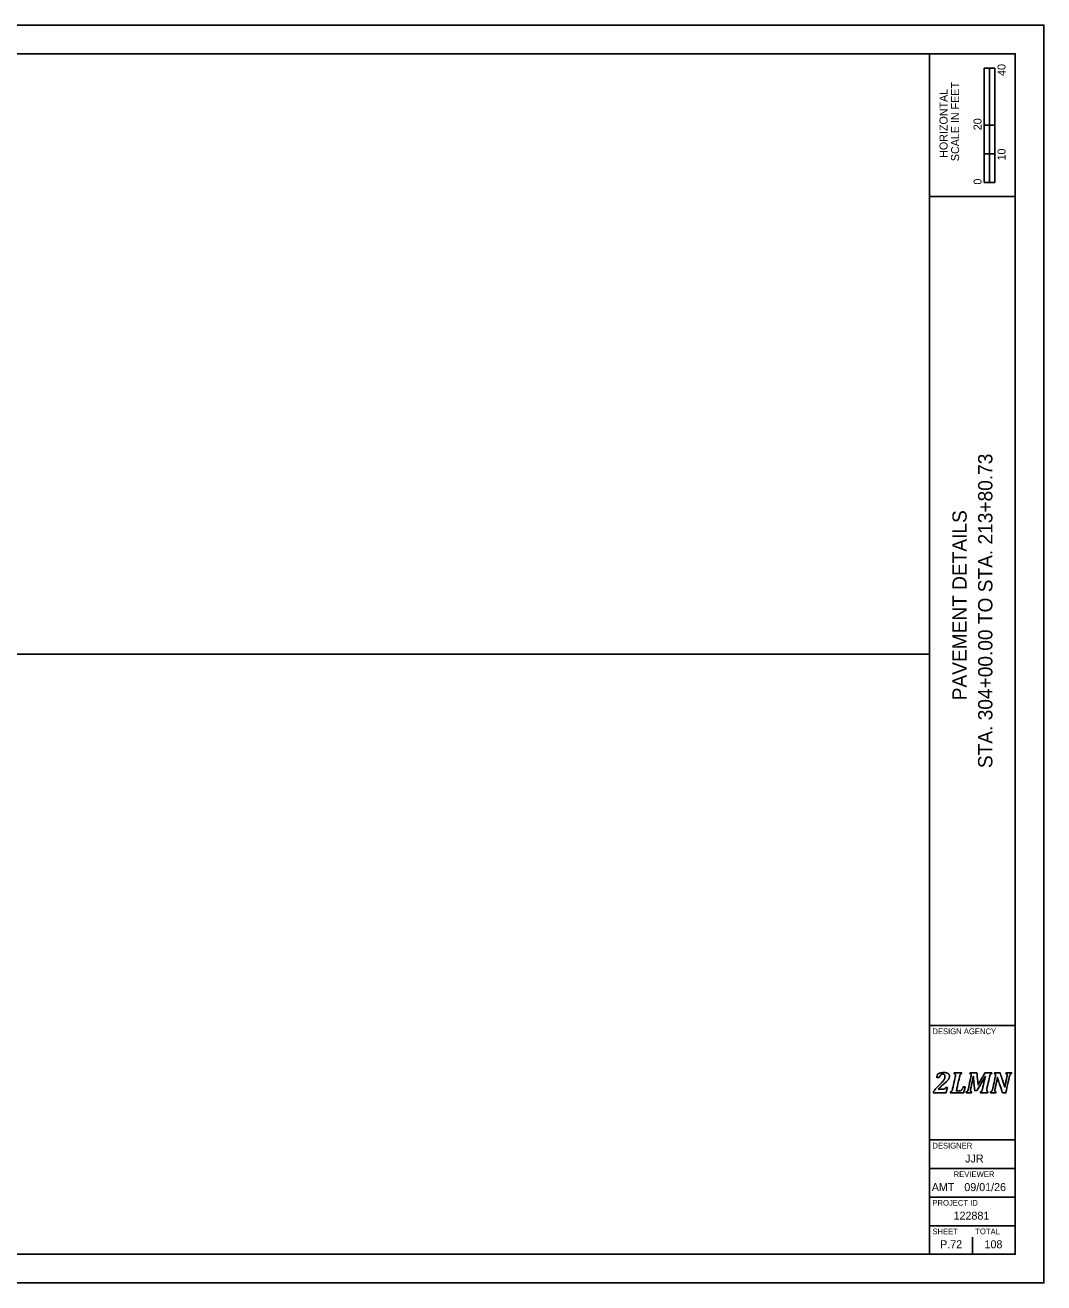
# Model space of a CAD drawing. Extents: x -1.6 to 34, y 0 to 22.
# Drawn here: x 16.18 to 34, y 0 to 22 of the extents above; entities that cross this region are included whole.
import ezdxf

# ---------------------------------------------------------------- set-up
doc = ezdxf.new("R2010")
doc.units = 0
for name, color, linetype in [('SH_Border', 7, 'Continuous'), ('SH_Cut_Line', 7, 'Continuous'), ('SH_Data', 7, 'Continuous')]:
    doc.layers.add(name, color=color, linetype=linetype)

msp = doc.modelspace()

# ---------------------------------------------------------------- linework, layer by layer
at = {"layer": 'SH_Border'}
for p, q in [((32, 0.5), (32, 21.5)), ((32, 19), (33.5, 19)), ((1.5, 11), (32, 11)), ((32, 4.5), (33.5, 4.5)), ((32, 2.5), (33.5, 2.5)), ((32, 2), (33.5, 2)), ((32, 1.5), (33.5, 1.5)), ((32, 1), (33.5, 1))]:
    msp.add_line(p, q, dxfattribs=at)
msp.add_lwpolyline([(1.5, 21.5), (33.5, 21.5), (33.5, 0.5), (1.5, 0.5)], close=True, dxfattribs=at)
at = {"layer": 'SH_Cut_Line'}
msp.add_lwpolyline([(0, 0), (34, 0), (34, 22), (0, 22)], close=True, dxfattribs=at)
at = {"layer": 'SH_Data'}
for p, q in [((32.957, 19.25), (32.957, 21.25)), ((33.144, 21.25), (32.957, 21.25)), ((32.957, 20.25), (32.957, 21.25)), ((32.957, 21.25), (33.05, 21.25)), ((33.05, 21.25), (33.051, 21.25)), ((33.051, 21.25), (33.051, 20.25)), ((33.144, 21.25), (33.144, 19.25)), ((33.051, 20.25), (32.957, 20.25)), ((33.143, 20.25), (33.05, 20.25)), ((33.05, 20.25), (33.05, 19.75)), ((33.143, 19.75), (33.143, 20.25)), ((33.05, 19.75), (32.957, 19.75)), ((32.957, 19.75), (32.957, 19.25)), ((33.05, 19.25), (33.05, 19.75)), ((33.05, 19.75), (33.143, 19.75)), ((33.144, 19.25), (32.957, 19.25)), ((32.957, 19.25), (33.05, 19.25)), ((32.75, 3.5), (32.75, 3.5)), ((32.375, 0.675), (32.375, 0.675)), ((32.75, 0.5), (32.75, 0.8))]:
    msp.add_line(p, q, dxfattribs=at)
for points in [[(32.237, 3.388), (32.246, 3.388), (32.253, 3.389), (32.258, 3.39), (32.263, 3.392), (32.267, 3.394), (32.27, 3.397), (32.273, 3.401), (32.277, 3.408), (32.281, 3.417), (32.281, 3.417), (32.312, 3.417), (32.312, 3.417), (32.312, 3.417), (32.29, 3.326), (32.29, 3.326), (32.29, 3.326), (32.066, 3.326), (32.066, 3.326), (32.066, 3.326), (32.069, 3.343), (32.069, 3.343), (32.078, 3.358), (32.091, 3.375), (32.106, 3.394), (32.122, 3.412), (32.144, 3.435), (32.172, 3.462), (32.197, 3.486), (32.217, 3.506), (32.23, 3.521), (32.243, 3.537), (32.253, 3.551), (32.259, 3.566), (32.266, 3.58), (32.269, 3.595), (32.269, 3.61), (32.269, 3.622), (32.266, 3.632), (32.26, 3.64), (32.253, 3.647), (32.245, 3.65), (32.234, 3.65), (32.22, 3.65), (32.208, 3.646), (32.198, 3.636), (32.188, 3.627), (32.18, 3.613), (32.172, 3.593), (32.172, 3.593), (32.126, 3.593), (32.126, 3.593), (32.126, 3.593), (32.14, 3.654), (32.14, 3.654), (32.166, 3.663), (32.188, 3.669), (32.205, 3.673), (32.223, 3.676), (32.24, 3.678), (32.258, 3.678), (32.278, 3.678), (32.295, 3.675), (32.309, 3.669), (32.322, 3.664), (32.332, 3.656), (32.339, 3.646), (32.345, 3.637), (32.348, 3.626), (32.348, 3.613), (32.348, 3.602), (32.346, 3.591), (32.342, 3.581), (32.339, 3.571), (32.333, 3.56), (32.324, 3.549), (32.315, 3.539), (32.304, 3.526), (32.289, 3.513), (32.275, 3.499), (32.254, 3.482), (32.228, 3.46), (32.216, 3.45), (32.202, 3.438), (32.188, 3.425), (32.174, 3.412), (32.162, 3.4), (32.154, 3.391), (32.154, 3.391), (32.153, 3.388), (32.153, 3.388), (32.153, 3.388), (32.237, 3.388), (32.237, 3.388)], [(32.237, 3.388), (32.237, 3.388), (32.153, 3.388), (32.153, 3.388), (32.153, 3.388), (32.154, 3.391), (32.154, 3.391), (32.162, 3.4), (32.174, 3.412), (32.188, 3.425), (32.202, 3.438), (32.216, 3.45), (32.228, 3.46), (32.254, 3.482), (32.275, 3.499), (32.289, 3.513), (32.304, 3.526), (32.315, 3.539), (32.324, 3.549), (32.333, 3.56), (32.339, 3.571), (32.342, 3.581), (32.346, 3.591), (32.348, 3.602), (32.348, 3.613), (32.348, 3.626), (32.345, 3.637), (32.339, 3.646), (32.332, 3.656), (32.322, 3.664), (32.309, 3.669), (32.295, 3.675), (32.278, 3.678), (32.258, 3.678), (32.24, 3.678), (32.223, 3.676), (32.205, 3.673), (32.188, 3.669), (32.166, 3.663), (32.14, 3.654), (32.14, 3.654), (32.126, 3.593), (32.126, 3.593), (32.126, 3.593), (32.172, 3.593), (32.172, 3.593), (32.18, 3.613), (32.188, 3.627), (32.198, 3.636), (32.208, 3.646), (32.22, 3.65), (32.234, 3.65), (32.245, 3.65), (32.253, 3.647), (32.26, 3.64), (32.266, 3.632), (32.269, 3.622), (32.269, 3.61), (32.269, 3.595), (32.266, 3.58), (32.259, 3.566), (32.253, 3.551), (32.243, 3.537), (32.23, 3.521), (32.217, 3.506), (32.197, 3.486), (32.172, 3.462), (32.144, 3.435), (32.122, 3.412), (32.106, 3.394), (32.091, 3.375), (32.078, 3.358), (32.069, 3.343), (32.069, 3.343), (32.066, 3.326), (32.066, 3.326), (32.066, 3.326), (32.29, 3.326), (32.29, 3.326), (32.29, 3.326), (32.312, 3.417), (32.312, 3.417), (32.312, 3.417), (32.281, 3.417), (32.281, 3.417), (32.277, 3.408), (32.273, 3.401), (32.27, 3.397), (32.267, 3.394), (32.263, 3.392), (32.258, 3.39), (32.253, 3.389), (32.246, 3.388), (32.237, 3.388)], [(32.518, 3.356), (32.527, 3.356), (32.533, 3.357), (32.538, 3.358), (32.542, 3.36), (32.546, 3.362), (32.55, 3.365), (32.554, 3.368), (32.558, 3.372), (32.562, 3.377), (32.567, 3.382), (32.571, 3.388), (32.576, 3.397), (32.58, 3.405), (32.585, 3.415), (32.589, 3.427), (32.589, 3.427), (32.624, 3.427), (32.624, 3.427), (32.624, 3.427), (32.598, 3.326), (32.598, 3.326), (32.598, 3.326), (32.365, 3.326), (32.365, 3.326), (32.365, 3.326), (32.369, 3.343), (32.369, 3.343), (32.376, 3.345), (32.381, 3.348), (32.385, 3.351), (32.389, 3.355), (32.392, 3.36), (32.395, 3.366), (32.398, 3.373), (32.4, 3.382), (32.403, 3.395), (32.403, 3.395), (32.449, 3.605), (32.449, 3.605), (32.452, 3.615), (32.453, 3.625), (32.453, 3.635), (32.453, 3.642), (32.451, 3.647), (32.448, 3.651), (32.444, 3.654), (32.439, 3.656), (32.432, 3.657), (32.432, 3.657), (32.435, 3.674), (32.435, 3.674), (32.435, 3.674), (32.563, 3.674), (32.563, 3.674), (32.563, 3.674), (32.559, 3.657), (32.559, 3.657), (32.552, 3.655), (32.547, 3.652), (32.543, 3.649), (32.539, 3.645), (32.536, 3.64), (32.533, 3.634), (32.531, 3.627), (32.528, 3.618), (32.525, 3.605), (32.525, 3.605), (32.47, 3.356), (32.47, 3.356), (32.47, 3.356), (32.518, 3.356), (32.518, 3.356)], [(32.518, 3.356), (32.518, 3.356), (32.47, 3.356), (32.47, 3.356), (32.47, 3.356), (32.525, 3.605), (32.525, 3.605), (32.528, 3.618), (32.531, 3.627), (32.533, 3.634), (32.536, 3.64), (32.539, 3.645), (32.543, 3.649), (32.547, 3.652), (32.552, 3.655), (32.559, 3.657), (32.559, 3.657), (32.563, 3.674), (32.563, 3.674), (32.563, 3.674), (32.435, 3.674), (32.435, 3.674), (32.435, 3.674), (32.432, 3.657), (32.432, 3.657), (32.439, 3.656), (32.444, 3.654), (32.448, 3.651), (32.451, 3.647), (32.453, 3.642), (32.453, 3.635), (32.453, 3.625), (32.452, 3.615), (32.449, 3.605), (32.449, 3.605), (32.403, 3.395), (32.403, 3.395), (32.4, 3.382), (32.398, 3.373), (32.395, 3.366), (32.392, 3.36), (32.389, 3.355), (32.385, 3.351), (32.381, 3.348), (32.376, 3.345), (32.369, 3.343), (32.369, 3.343), (32.365, 3.326), (32.365, 3.326), (32.365, 3.326), (32.598, 3.326), (32.598, 3.326), (32.598, 3.326), (32.624, 3.427), (32.624, 3.427), (32.624, 3.427), (32.589, 3.427), (32.589, 3.427), (32.585, 3.415), (32.58, 3.405), (32.576, 3.397), (32.571, 3.388), (32.567, 3.382), (32.562, 3.377), (32.558, 3.372), (32.554, 3.368), (32.55, 3.365), (32.546, 3.362), (32.542, 3.36), (32.538, 3.358), (32.533, 3.357), (32.527, 3.356), (32.518, 3.356)], [(32.829, 3.674), (32.829, 3.674), (32.849, 3.461), (32.849, 3.461), (32.849, 3.461), (32.969, 3.674), (32.969, 3.674), (32.969, 3.674), (33.087, 3.674), (33.087, 3.674), (33.087, 3.674), (33.084, 3.657), (33.084, 3.657), (33.077, 3.655), (33.071, 3.652), (33.067, 3.649), (33.064, 3.645), (33.06, 3.64), (33.058, 3.634), (33.055, 3.627), (33.052, 3.618), (33.05, 3.605), (33.05, 3.605), (33.003, 3.395), (33.003, 3.395), (33.002, 3.39), (33.002, 3.387), (33.001, 3.384), (33.001, 3.382), (33.001, 3.379), (33, 3.376), (33, 3.373), (33, 3.369), (33, 3.365), (33, 3.358), (33.002, 3.353), (33.005, 3.349), (33.008, 3.346), (33.014, 3.344), (33.021, 3.343), (33.021, 3.343), (33.018, 3.326), (33.018, 3.326), (33.018, 3.326), (32.89, 3.326), (32.89, 3.326), (32.89, 3.326), (32.893, 3.343), (32.893, 3.343), (32.9, 3.345), (32.906, 3.348), (32.91, 3.351), (32.914, 3.355), (32.917, 3.36), (32.919, 3.366), (32.922, 3.373), (32.925, 3.382), (32.928, 3.395), (32.928, 3.395), (32.951, 3.502), (32.951, 3.502), (32.954, 3.513), (32.957, 3.529), (32.962, 3.548), (32.967, 3.568), (32.972, 3.588), (32.978, 3.609), (32.978, 3.609), (32.973, 3.609), (32.973, 3.609), (32.965, 3.594), (32.957, 3.579), (32.948, 3.563), (32.948, 3.563), (32.833, 3.364), (32.833, 3.364), (32.833, 3.364), (32.792, 3.364), (32.792, 3.364), (32.792, 3.364), (32.775, 3.518), (32.775, 3.518), (32.773, 3.537), (32.772, 3.554), (32.77, 3.569), (32.769, 3.583), (32.768, 3.597), (32.768, 3.611), (32.768, 3.611), (32.764, 3.611), (32.764, 3.611), (32.761, 3.596), (32.758, 3.578), (32.755, 3.558), (32.751, 3.538), (32.747, 3.521), (32.744, 3.507), (32.744, 3.507), (32.72, 3.395), (32.72, 3.395), (32.719, 3.39), (32.718, 3.387), (32.718, 3.384), (32.717, 3.382), (32.717, 3.379), (32.717, 3.376), (32.717, 3.373), (32.716, 3.369), (32.716, 3.365), (32.716, 3.358), (32.718, 3.353), (32.721, 3.349), (32.725, 3.346), (32.73, 3.344), (32.738, 3.343), (32.738, 3.343), (32.734, 3.326), (32.734, 3.326), (32.734, 3.326), (32.641, 3.326), (32.641, 3.326), (32.641, 3.326), (32.644, 3.343), (32.644, 3.343), (32.651, 3.345), (32.657, 3.348), (32.661, 3.351), (32.665, 3.355), (32.668, 3.36), (32.67, 3.366), (32.673, 3.373), (32.676, 3.382), (32.679, 3.395), (32.679, 3.395), (32.725, 3.605), (32.725, 3.605), (32.727, 3.615), (32.728, 3.625), (32.728, 3.635), (32.728, 3.642), (32.727, 3.647), (32.723, 3.651), (32.72, 3.654), (32.715, 3.656), (32.707, 3.657), (32.707, 3.657), (32.711, 3.674), (32.711, 3.674), (32.711, 3.674), (32.829, 3.674), (32.829, 3.674)], [(32.829, 3.674), (32.829, 3.674), (32.711, 3.674), (32.711, 3.674), (32.711, 3.674), (32.707, 3.657), (32.707, 3.657), (32.715, 3.656), (32.72, 3.654), (32.723, 3.651), (32.727, 3.647), (32.728, 3.642), (32.728, 3.635), (32.728, 3.625), (32.727, 3.615), (32.725, 3.605), (32.725, 3.605), (32.679, 3.395), (32.679, 3.395), (32.676, 3.382), (32.673, 3.373), (32.67, 3.366), (32.668, 3.36), (32.665, 3.355), (32.661, 3.351), (32.657, 3.348), (32.651, 3.345), (32.644, 3.343), (32.644, 3.343), (32.641, 3.326), (32.641, 3.326), (32.641, 3.326), (32.734, 3.326), (32.734, 3.326), (32.734, 3.326), (32.738, 3.343), (32.738, 3.343), (32.73, 3.344), (32.725, 3.346), (32.721, 3.349), (32.718, 3.353), (32.716, 3.358), (32.716, 3.365), (32.716, 3.369), (32.717, 3.373), (32.717, 3.376), (32.717, 3.379), (32.717, 3.382), (32.718, 3.384), (32.718, 3.387), (32.719, 3.39), (32.72, 3.395), (32.72, 3.395), (32.744, 3.507), (32.744, 3.507), (32.747, 3.521), (32.751, 3.538), (32.755, 3.558), (32.758, 3.578), (32.761, 3.596), (32.764, 3.611), (32.764, 3.611), (32.768, 3.611), (32.768, 3.611), (32.768, 3.597), (32.769, 3.583), (32.77, 3.569), (32.772, 3.554), (32.773, 3.537), (32.775, 3.518), (32.775, 3.518), (32.792, 3.364), (32.792, 3.364), (32.792, 3.364), (32.833, 3.364), (32.833, 3.364), (32.833, 3.364), (32.948, 3.563), (32.948, 3.563), (32.957, 3.579), (32.965, 3.594), (32.973, 3.609), (32.973, 3.609), (32.978, 3.609), (32.978, 3.609), (32.972, 3.588), (32.967, 3.568), (32.962, 3.548), (32.957, 3.529), (32.954, 3.513), (32.951, 3.502), (32.951, 3.502), (32.928, 3.395), (32.928, 3.395), (32.925, 3.382), (32.922, 3.373), (32.919, 3.366), (32.917, 3.36), (32.914, 3.355), (32.91, 3.351), (32.906, 3.348), (32.9, 3.345), (32.893, 3.343), (32.893, 3.343), (32.89, 3.326), (32.89, 3.326), (32.89, 3.326), (33.018, 3.326), (33.018, 3.326), (33.018, 3.326), (33.021, 3.343), (33.021, 3.343), (33.014, 3.344), (33.008, 3.346), (33.005, 3.349), (33.002, 3.353), (33, 3.358), (33, 3.365), (33, 3.369), (33, 3.373), (33, 3.376), (33.001, 3.379), (33.001, 3.382), (33.001, 3.384), (33.002, 3.387), (33.002, 3.39), (33.003, 3.395), (33.003, 3.395), (33.05, 3.605), (33.05, 3.605), (33.052, 3.618), (33.055, 3.627), (33.058, 3.634), (33.06, 3.64), (33.064, 3.645), (33.067, 3.649), (33.071, 3.652), (33.077, 3.655), (33.084, 3.657), (33.084, 3.657), (33.087, 3.674), (33.087, 3.674), (33.087, 3.674), (32.969, 3.674), (32.969, 3.674), (32.969, 3.674), (32.849, 3.461), (32.849, 3.461), (32.849, 3.461), (32.829, 3.674), (32.829, 3.674)], [(33.137, 3.674), (33.137, 3.674), (33.234, 3.674), (33.234, 3.674), (33.234, 3.674), (33.283, 3.53), (33.283, 3.53), (33.296, 3.49), (33.307, 3.456), (33.315, 3.426), (33.315, 3.426), (33.318, 3.426), (33.318, 3.426), (33.323, 3.455), (33.329, 3.488), (33.337, 3.523), (33.337, 3.523), (33.355, 3.605), (33.355, 3.605), (33.357, 3.615), (33.358, 3.625), (33.358, 3.635), (33.358, 3.642), (33.357, 3.647), (33.353, 3.651), (33.35, 3.654), (33.345, 3.656), (33.337, 3.657), (33.337, 3.657), (33.341, 3.674), (33.341, 3.674), (33.341, 3.674), (33.434, 3.674), (33.434, 3.674), (33.434, 3.674), (33.431, 3.657), (33.431, 3.657), (33.424, 3.655), (33.418, 3.652), (33.414, 3.649), (33.41, 3.645), (33.407, 3.64), (33.405, 3.634), (33.402, 3.627), (33.399, 3.618), (33.396, 3.605), (33.396, 3.605), (33.335, 3.326), (33.335, 3.326), (33.335, 3.326), (33.277, 3.326), (33.277, 3.326), (33.277, 3.326), (33.216, 3.504), (33.216, 3.504), (33.211, 3.518), (33.207, 3.531), (33.204, 3.543), (33.2, 3.556), (33.195, 3.571), (33.19, 3.59), (33.19, 3.59), (33.186, 3.59), (33.186, 3.59), (33.185, 3.579), (33.182, 3.563), (33.179, 3.543), (33.175, 3.523), (33.17, 3.501), (33.165, 3.478), (33.165, 3.478), (33.147, 3.395), (33.147, 3.395), (33.146, 3.39), (33.145, 3.387), (33.145, 3.384), (33.144, 3.382), (33.144, 3.379), (33.144, 3.376), (33.143, 3.373), (33.143, 3.369), (33.143, 3.365), (33.143, 3.358), (33.145, 3.353), (33.148, 3.349), (33.152, 3.346), (33.157, 3.344), (33.164, 3.343), (33.164, 3.343), (33.161, 3.326), (33.161, 3.326), (33.161, 3.326), (33.067, 3.326), (33.067, 3.326), (33.067, 3.326), (33.071, 3.343), (33.071, 3.343), (33.078, 3.345), (33.083, 3.348), (33.087, 3.351), (33.091, 3.355), (33.094, 3.36), (33.097, 3.366), (33.1, 3.373), (33.102, 3.382), (33.105, 3.395), (33.105, 3.395), (33.151, 3.605), (33.151, 3.605), (33.154, 3.615), (33.155, 3.625), (33.155, 3.635), (33.155, 3.642), (33.153, 3.647), (33.15, 3.651), (33.146, 3.654), (33.141, 3.656), (33.134, 3.657), (33.134, 3.657), (33.137, 3.674), (33.137, 3.674)], [(33.137, 3.674), (33.137, 3.674), (33.134, 3.657), (33.134, 3.657), (33.141, 3.656), (33.146, 3.654), (33.15, 3.651), (33.153, 3.647), (33.155, 3.642), (33.155, 3.635), (33.155, 3.625), (33.154, 3.615), (33.151, 3.605), (33.151, 3.605), (33.105, 3.395), (33.105, 3.395), (33.102, 3.382), (33.1, 3.373), (33.097, 3.366), (33.094, 3.36), (33.091, 3.355), (33.087, 3.351), (33.083, 3.348), (33.078, 3.345), (33.071, 3.343), (33.071, 3.343), (33.067, 3.326), (33.067, 3.326), (33.067, 3.326), (33.161, 3.326), (33.161, 3.326), (33.161, 3.326), (33.164, 3.343), (33.164, 3.343), (33.157, 3.344), (33.152, 3.346), (33.148, 3.349), (33.145, 3.353), (33.143, 3.358), (33.143, 3.365), (33.143, 3.369), (33.143, 3.373), (33.144, 3.376), (33.144, 3.379), (33.144, 3.382), (33.145, 3.384), (33.145, 3.387), (33.146, 3.39), (33.147, 3.395), (33.147, 3.395), (33.165, 3.478), (33.165, 3.478), (33.17, 3.501), (33.175, 3.523), (33.179, 3.543), (33.182, 3.563), (33.185, 3.579), (33.186, 3.59), (33.186, 3.59), (33.19, 3.59), (33.19, 3.59), (33.195, 3.571), (33.2, 3.556), (33.204, 3.543), (33.207, 3.531), (33.211, 3.518), (33.216, 3.504), (33.216, 3.504), (33.277, 3.326), (33.277, 3.326), (33.277, 3.326), (33.335, 3.326), (33.335, 3.326), (33.335, 3.326), (33.396, 3.605), (33.396, 3.605), (33.399, 3.618), (33.402, 3.627), (33.405, 3.634), (33.407, 3.64), (33.41, 3.645), (33.414, 3.649), (33.418, 3.652), (33.424, 3.655), (33.431, 3.657), (33.431, 3.657), (33.434, 3.674), (33.434, 3.674), (33.434, 3.674), (33.341, 3.674), (33.341, 3.674), (33.341, 3.674), (33.337, 3.657), (33.337, 3.657), (33.345, 3.656), (33.35, 3.654), (33.353, 3.651), (33.357, 3.647), (33.358, 3.642), (33.358, 3.635), (33.358, 3.625), (33.357, 3.615), (33.355, 3.605), (33.355, 3.605), (33.337, 3.523), (33.337, 3.523), (33.329, 3.488), (33.323, 3.455), (33.318, 3.426), (33.318, 3.426), (33.315, 3.426), (33.315, 3.426), (33.307, 3.456), (33.296, 3.49), (33.283, 3.53), (33.283, 3.53), (33.234, 3.674), (33.234, 3.674), (33.234, 3.674), (33.137, 3.674), (33.137, 3.674)]]:
    msp.add_open_spline(points, degree=3, dxfattribs=at)

# ---------------------------------------------------------------- texts
for s, height, p in [('40', 0.14, (33.33, 21.112)), ('SCALE IN FEET', 0.14, (32.517, 19.621)), ('HORIZONTAL', 0.14, (32.315, 19.679)), ('20', 0.14, (32.91, 20.162)), ('10', 0.14, (33.33, 19.633)), ('0', 0.14, (32.91, 19.211)), ('STA. 304+00.00 TO STA. 213+80.73', 0.25, (33.1, 9.004)), ('PAVEMENT DETAILS', 0.25, (32.65, 10.19))]:
    msp.add_text(s, height=height, rotation=90, dxfattribs=at).set_placement(p)
for s, height, p in [('DESIGN AGENCY', 0.1, (32.05, 4.35)), ('DESIGNER', 0.1, (32.05, 2.35)), ('JJR', 0.14, (32.624, 2.105)), ('REVIEWER', 0.1, (32.422, 1.85)), ('AMT', 0.14, (32.039, 1.605)), ('09/01/26', 0.14, (32.609, 1.605)), ('PROJECT ID', 0.1, (32.05, 1.35)), ('122881', 0.14, (32.421, 1.105)), ('SHEET', 0.1, (32.05, 0.85)), ('TOTAL', 0.1, (32.8, 0.85)), ('P.72', 0.14, (32.185, 0.605)), ('108', 0.14, (32.962, 0.605))]:
    msp.add_text(s, height=height, dxfattribs=at).set_placement(p)

doc.saveas('drawing.dxf')
